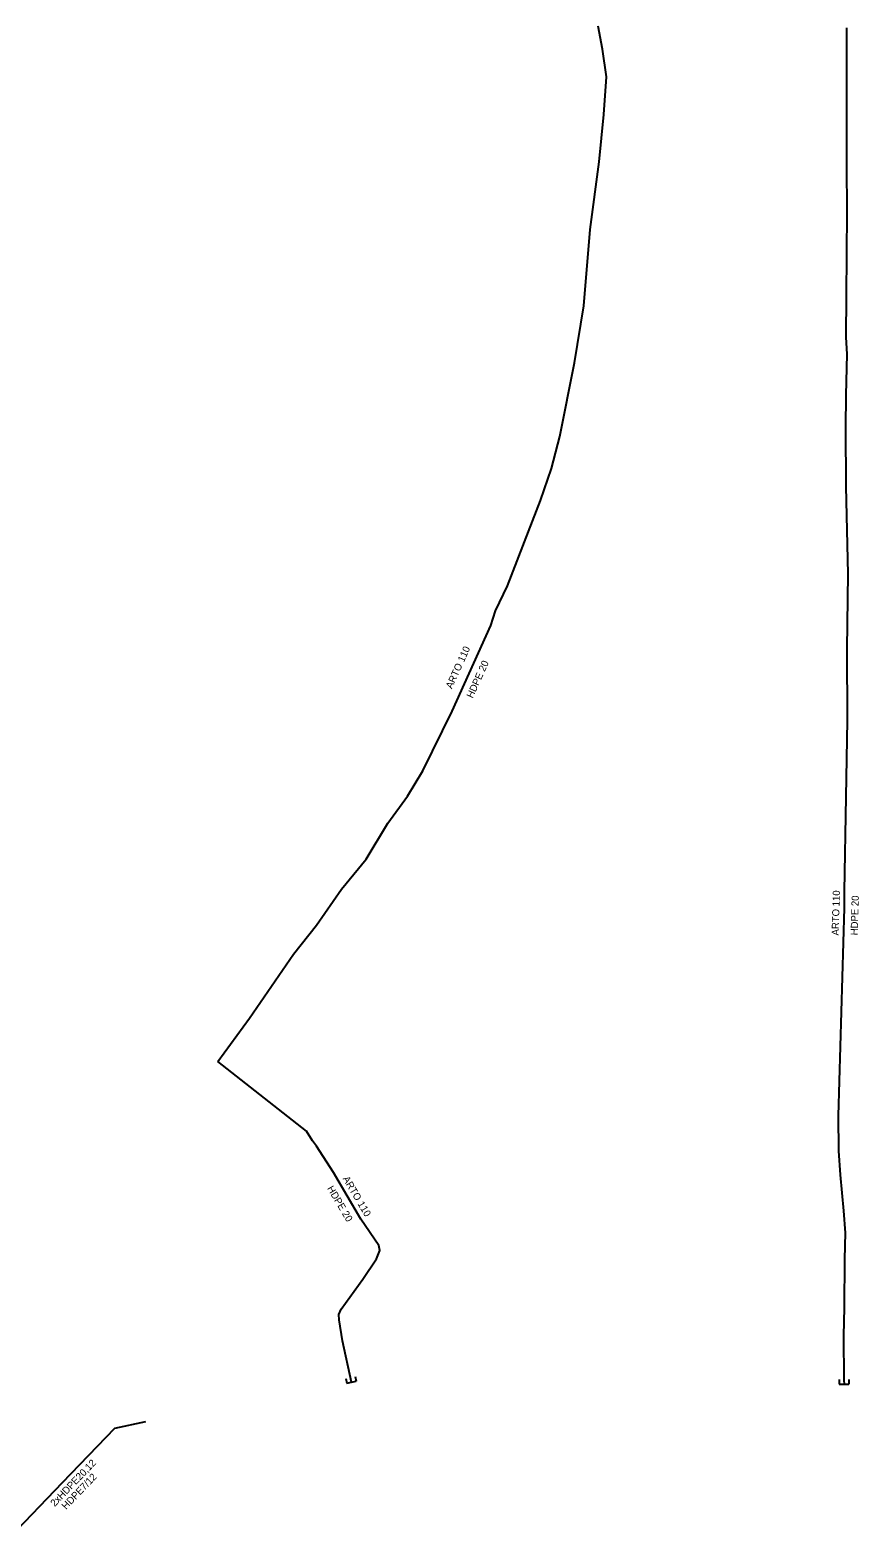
# Model space of a CAD drawing. Extents: x -651943 to -618711, y -1138561 to -1100552.
# Drawn here: x -640577.1 to -640490, y -1115587.8 to -1115429.4 of the extents above; entities that cross this region are included whole.
import ezdxf

# ---------------------------------------------------------------- set-up
doc = ezdxf.new("R2010")
doc.units = 0
for name, color, linetype in [('KT optika', 7, 'Continuous'), ('KT trasa', 7, 'Continuous'), ('KT zařízení', 7, 'Continuous')]:
    doc.layers.add(name, color=color, linetype=linetype)

# ---------------------------------------------------------------- blocks, each defined once
blk = doc.blocks.new('TVREZ_9')
at = {"layer": 'KT zařízení'}
for p, q in [((-0.05, 0.05), (0, 0.05)), ((0, -0.05), (0, 0.05)), ((-0.05, -0.05), (0, -0.05))]:
    blk.add_line(p, q, dxfattribs=at)
blk = doc.blocks.new('TVREZ_8')
at = {"layer": 'KT zařízení'}
blk.add_blockref('TVREZ_9', (0, 0), dxfattribs=at)

msp = doc.modelspace()

# ---------------------------------------------------------------- linework, layer by layer
at = {"layer": 'KT optika'}
for p, q in [((-640573.7, -1115582.01), (-640568.2, -1115576.29)), ((-640568.2, -1115576.29), (-640564.94, -1115575.6)), ((-640579.27, -1115587.83), (-640573.7, -1115582.01))]:
    msp.add_line(p, q, dxfattribs=at)
for points in [[(-640557.38, -1115537.77), (-640554.05, -1115533.24), (-640549.42, -1115526.52), (-640547.01, -1115523.44), (-640544.39, -1115519.69), (-640541.81, -1115516.53), (-640539.52, -1115512.73), (-640537.45, -1115509.92), (-640535.84, -1115507.25), (-640532.75, -1115500.97), (-640528.68, -1115491.96), (-640528.21, -1115490.42), (-640526.95, -1115487.79), (-640524.74, -1115482.09), (-640523.47, -1115478.83), (-640522.33, -1115475.46), (-640521.43, -1115472.1), (-640519.9, -1115464.39), (-640518.93, -1115458.38), (-640518.26, -1115450.36), (-640517.29, -1115443.24), (-640516.8, -1115438.28), (-640516.52, -1115434.33), (-640516.97, -1115431.41), (-640517.41, -1115429.01)], [(-640491.31, -1115429.18), (-640491.3, -1115443.58), (-640491.28, -1115448.53), (-640491.34, -1115457.36), (-640491.37, -1115461.67), (-640491.27, -1115463.45), (-640491.36, -1115467.78), (-640491.4, -1115471.18), (-640491.38, -1115477.35), (-640491.18, -1115486.54), (-640491.26, -1115494.44), (-640491.25, -1115501.94), (-640491.36, -1115509.96), (-640491.55, -1115519.92), (-640491.55, -1115521.64), (-640492.18, -1115543.48), (-640492.14, -1115547.16), (-640491.96, -1115549.7), (-640491.61, -1115553.46), (-640491.45, -1115555.8), (-640491.51, -1115558.56), (-640491.56, -1115563.67), (-640491.62, -1115566.58), (-640491.59, -1115571.25)], [(-640543.33, -1115571.48), (-640544.29, -1115567.13), (-640544.64, -1115564.92), (-640544.66, -1115564.35), (-640544.41, -1115563.8), (-640542.14, -1115560.66), (-640540.7, -1115558.52), (-640540.37, -1115557.64), (-640540.48, -1115557.11), (-640542.35, -1115554.36), (-640545.24, -1115549.46), (-640547, -1115546.69), (-640547.42, -1115546.13), (-640548.08, -1115545.1), (-640557.38, -1115537.77)]]:
    msp.add_lwpolyline(points, dxfattribs=at)
at = {"layer": 'KT trasa'}
for p, q in [((-640573.7, -1115582.01), (-640568.2, -1115576.29)), ((-640568.2, -1115576.29), (-640564.94, -1115575.6)), ((-640579.27, -1115587.83), (-640573.7, -1115582.01))]:
    msp.add_line(p, q, dxfattribs=at)
for points in [[(-640557.38, -1115537.77), (-640554.05, -1115533.24), (-640549.42, -1115526.52), (-640547.01, -1115523.44), (-640544.39, -1115519.69), (-640541.81, -1115516.53), (-640539.52, -1115512.73), (-640537.45, -1115509.92), (-640535.84, -1115507.25), (-640532.75, -1115500.97), (-640528.68, -1115491.96), (-640528.21, -1115490.42), (-640526.95, -1115487.79), (-640524.74, -1115482.09), (-640523.47, -1115478.83), (-640522.33, -1115475.46), (-640521.43, -1115472.1), (-640519.9, -1115464.39), (-640518.93, -1115458.38), (-640518.26, -1115450.36), (-640517.29, -1115443.24), (-640516.8, -1115438.28), (-640516.52, -1115434.33), (-640516.97, -1115431.41), (-640517.41, -1115429.01)], [(-640491.31, -1115429.18), (-640491.3, -1115443.58), (-640491.28, -1115448.53), (-640491.34, -1115457.36), (-640491.37, -1115461.67), (-640491.27, -1115463.45), (-640491.36, -1115467.78), (-640491.4, -1115471.18), (-640491.38, -1115477.35), (-640491.18, -1115486.54), (-640491.26, -1115494.44), (-640491.25, -1115501.94), (-640491.36, -1115509.96), (-640491.55, -1115519.92), (-640491.55, -1115521.64), (-640492.18, -1115543.48), (-640492.14, -1115547.16), (-640491.96, -1115549.7), (-640491.61, -1115553.46), (-640491.45, -1115555.8), (-640491.51, -1115558.56), (-640491.56, -1115563.67), (-640491.62, -1115566.58), (-640491.59, -1115571.25)], [(-640543.33, -1115571.48), (-640544.29, -1115567.13), (-640544.64, -1115564.92), (-640544.66, -1115564.35), (-640544.41, -1115563.8), (-640542.14, -1115560.66), (-640540.7, -1115558.52), (-640540.37, -1115557.64), (-640540.48, -1115557.11), (-640542.35, -1115554.36), (-640545.24, -1115549.46), (-640547, -1115546.69), (-640547.42, -1115546.13), (-640548.08, -1115545.1), (-640557.38, -1115537.77)]]:
    msp.add_lwpolyline(points, dxfattribs=at)
at = {"layer": 'KT zařízení'}
for p, q in [((-640573.7, -1115582.01), (-640568.2, -1115576.29)), ((-640568.2, -1115576.29), (-640564.94, -1115575.6)), ((-640579.27, -1115587.83), (-640573.7, -1115582.01))]:
    msp.add_line(p, q, dxfattribs=at)
for points in [[(-640557.38, -1115537.77), (-640554.05, -1115533.24), (-640549.42, -1115526.52), (-640547.01, -1115523.44), (-640544.39, -1115519.69), (-640541.81, -1115516.53), (-640539.52, -1115512.73), (-640537.45, -1115509.92), (-640535.84, -1115507.25), (-640532.75, -1115500.97), (-640528.68, -1115491.96), (-640528.21, -1115490.42), (-640526.95, -1115487.79), (-640524.74, -1115482.09), (-640523.47, -1115478.83), (-640522.33, -1115475.46), (-640521.43, -1115472.1), (-640519.9, -1115464.39), (-640518.93, -1115458.38), (-640518.26, -1115450.36), (-640517.29, -1115443.24), (-640516.8, -1115438.28), (-640516.52, -1115434.33), (-640516.97, -1115431.41), (-640517.41, -1115429.01)], [(-640491.31, -1115429.18), (-640491.3, -1115443.58), (-640491.28, -1115448.53), (-640491.34, -1115457.36), (-640491.37, -1115461.67), (-640491.27, -1115463.45), (-640491.36, -1115467.78), (-640491.4, -1115471.18), (-640491.38, -1115477.35), (-640491.18, -1115486.54), (-640491.26, -1115494.44), (-640491.25, -1115501.94), (-640491.36, -1115509.96), (-640491.55, -1115519.92), (-640491.55, -1115521.64), (-640492.18, -1115543.48), (-640492.14, -1115547.16), (-640491.96, -1115549.7), (-640491.61, -1115553.46), (-640491.45, -1115555.8), (-640491.51, -1115558.56), (-640491.56, -1115563.67), (-640491.62, -1115566.58), (-640491.59, -1115571.25), (-640491.56, -1115571.7)], [(-640543.33, -1115571.48), (-640544.29, -1115567.13), (-640544.64, -1115564.92), (-640544.66, -1115564.35), (-640544.41, -1115563.8), (-640542.14, -1115560.66), (-640540.7, -1115558.52), (-640540.37, -1115557.64), (-640540.48, -1115557.11), (-640542.35, -1115554.36), (-640545.24, -1115549.46), (-640547, -1115546.69), (-640547.42, -1115546.13), (-640548.08, -1115545.1), (-640557.38, -1115537.77)]]:
    msp.add_lwpolyline(points, dxfattribs=at)

# ---------------------------------------------------------------- block references
for p, xscale, yscale, rotation in [((-640543.33, -1115571.48), 10.000014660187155, 10.000014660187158, -77.09961302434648), ((-640491.56, -1115571.7), 10, 10, -90.00000000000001)]:
    msp.add_blockref('TVREZ_8', p, dxfattribs=dict(at, xscale=xscale, yscale=yscale, rotation=rotation))

# ---------------------------------------------------------------- texts
for s, rotation, p in [('ARTO 110', 65.6903, (-640532.79, -1115498.68)), ('HDPE 20', 65.6903, (-640530.6, -1115499.67)), ('ARTO 110', 88.3477, (-640492.13, -1115524.55)), ('HDPE 20', 88.3477, (-640490.13, -1115524.53)), ('ARTO 110', 300.5319, (-640544.29, -1115550.09)), ('HDPE 20', 300.5319, (-640545.93, -1115551.11)), ('2xHDPE20,12', 46.1233, (-640574.53, -1115584.6)), ('HDPE7/12', 46.1233, (-640573.34, -1115584.91))]:
    msp.add_text(s, height=0.75, rotation=rotation, dxfattribs=at).set_placement(p)

doc.saveas('drawing.dxf')
